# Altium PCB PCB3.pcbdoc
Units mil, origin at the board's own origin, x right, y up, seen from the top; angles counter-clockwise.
Board outline 1949.7 x 1974.5 mil, 4 copper layers (Top Layer, Inner1, Inner2, Bottom Layer); 20 components, 15 nets, 76 pads, 43 vias.
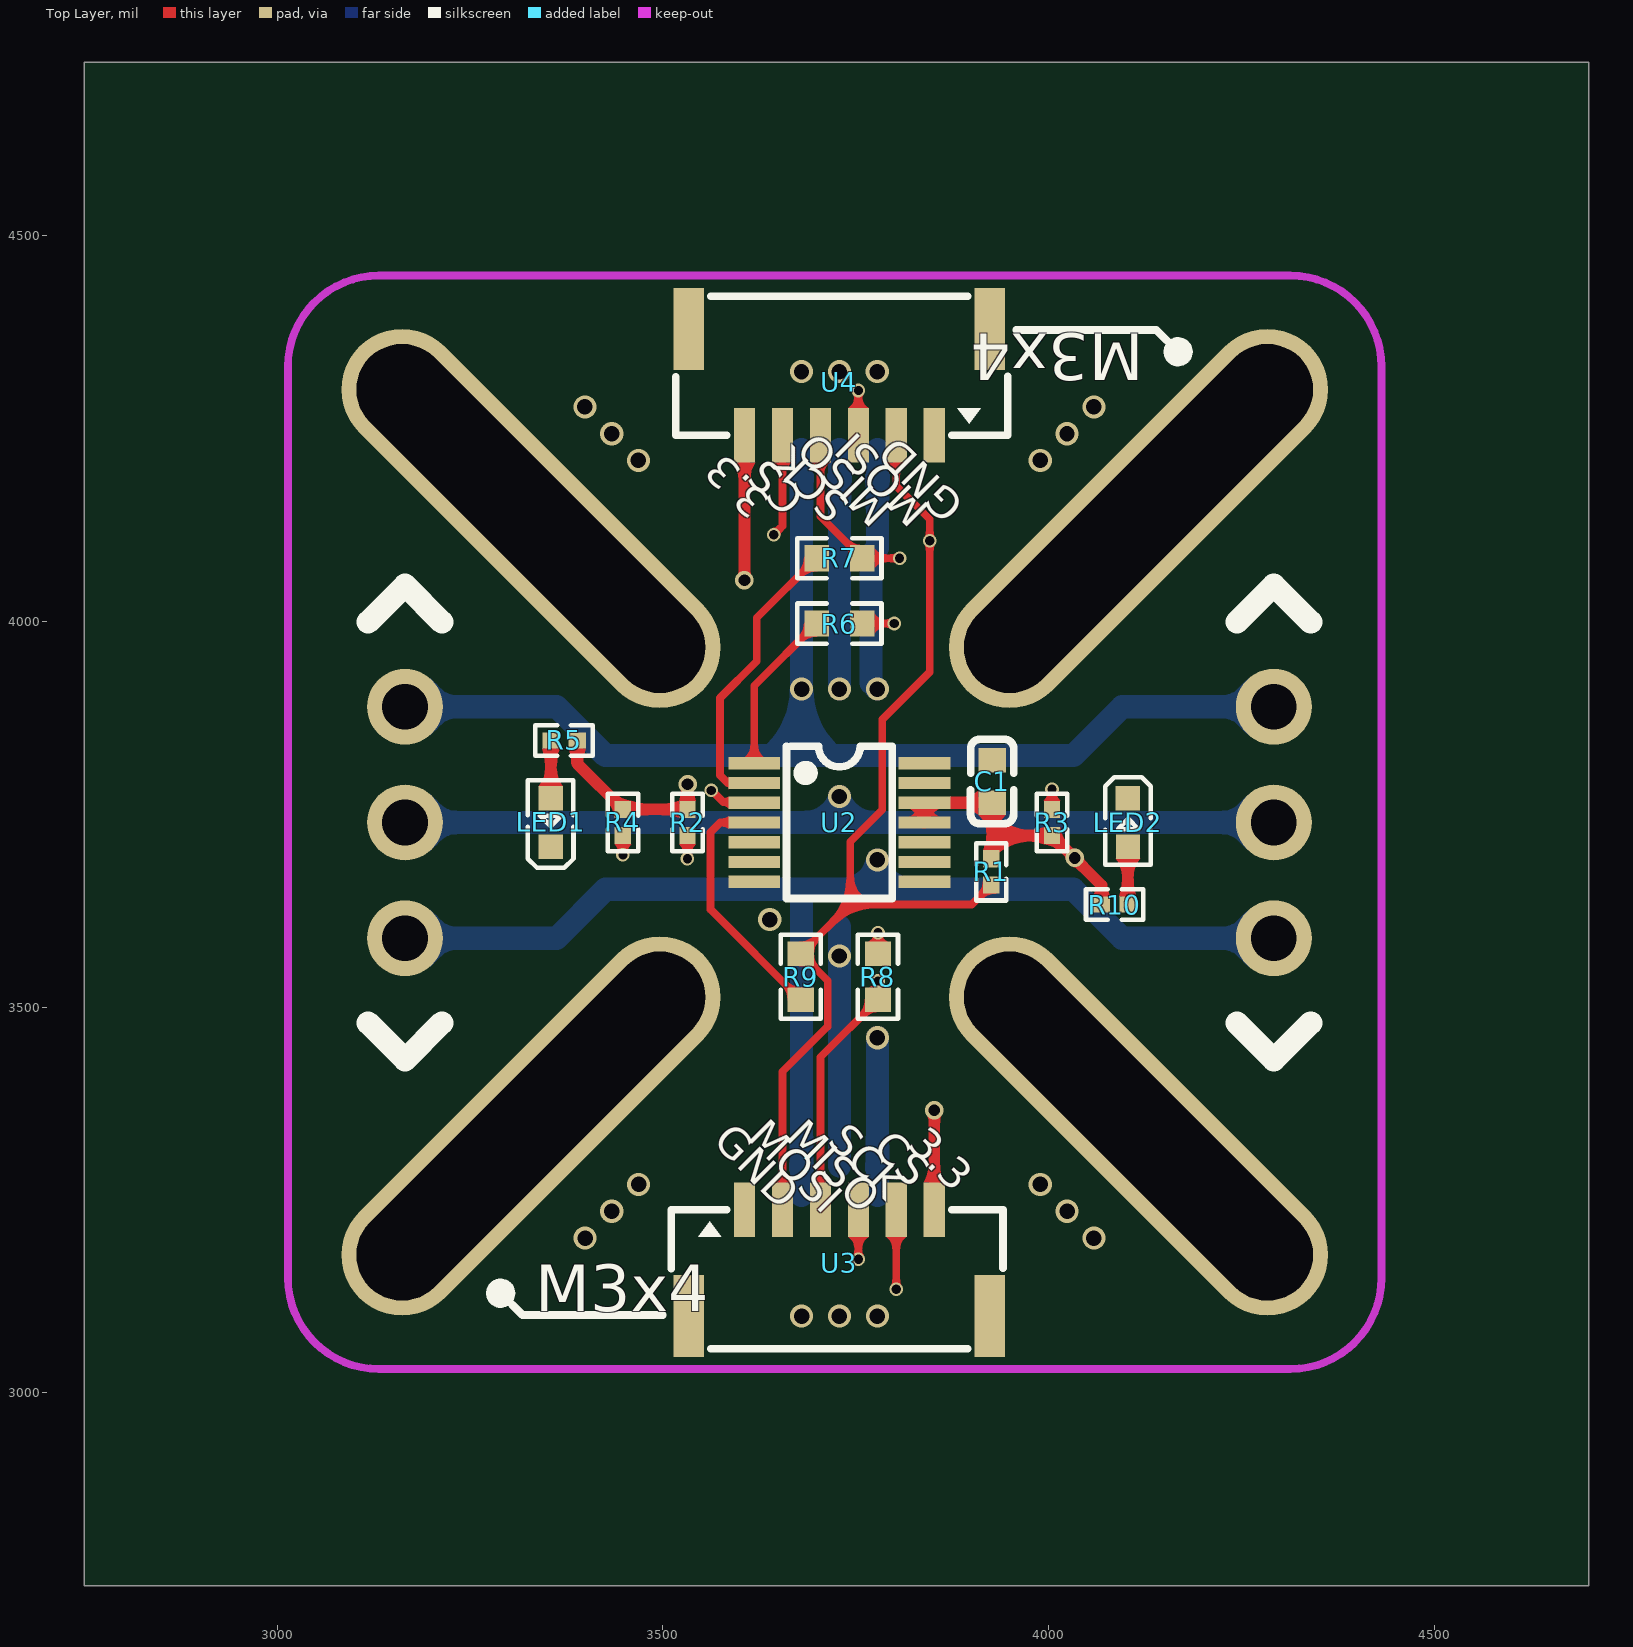
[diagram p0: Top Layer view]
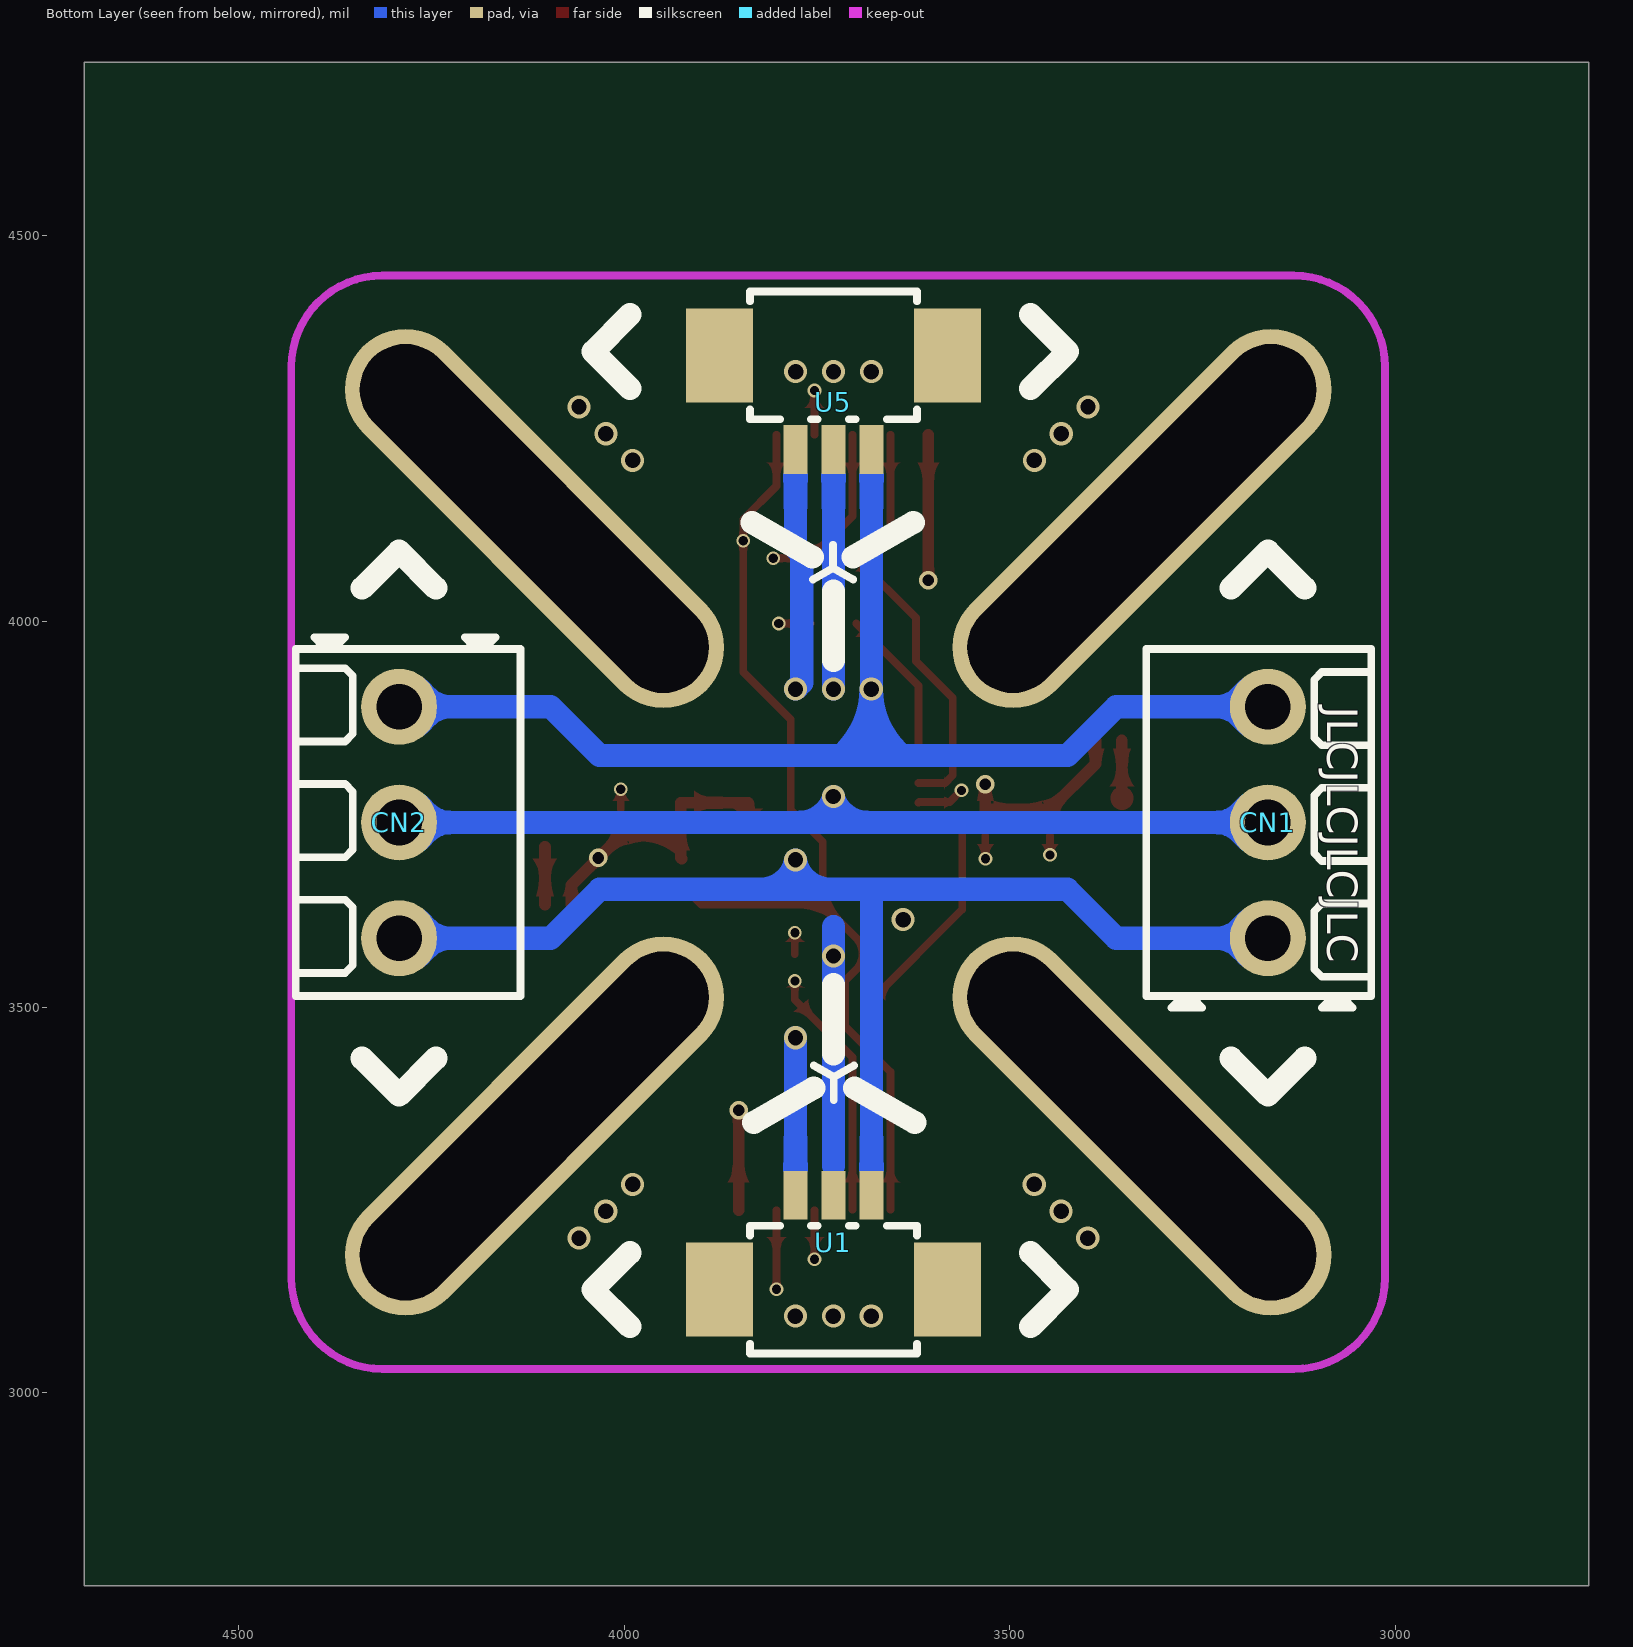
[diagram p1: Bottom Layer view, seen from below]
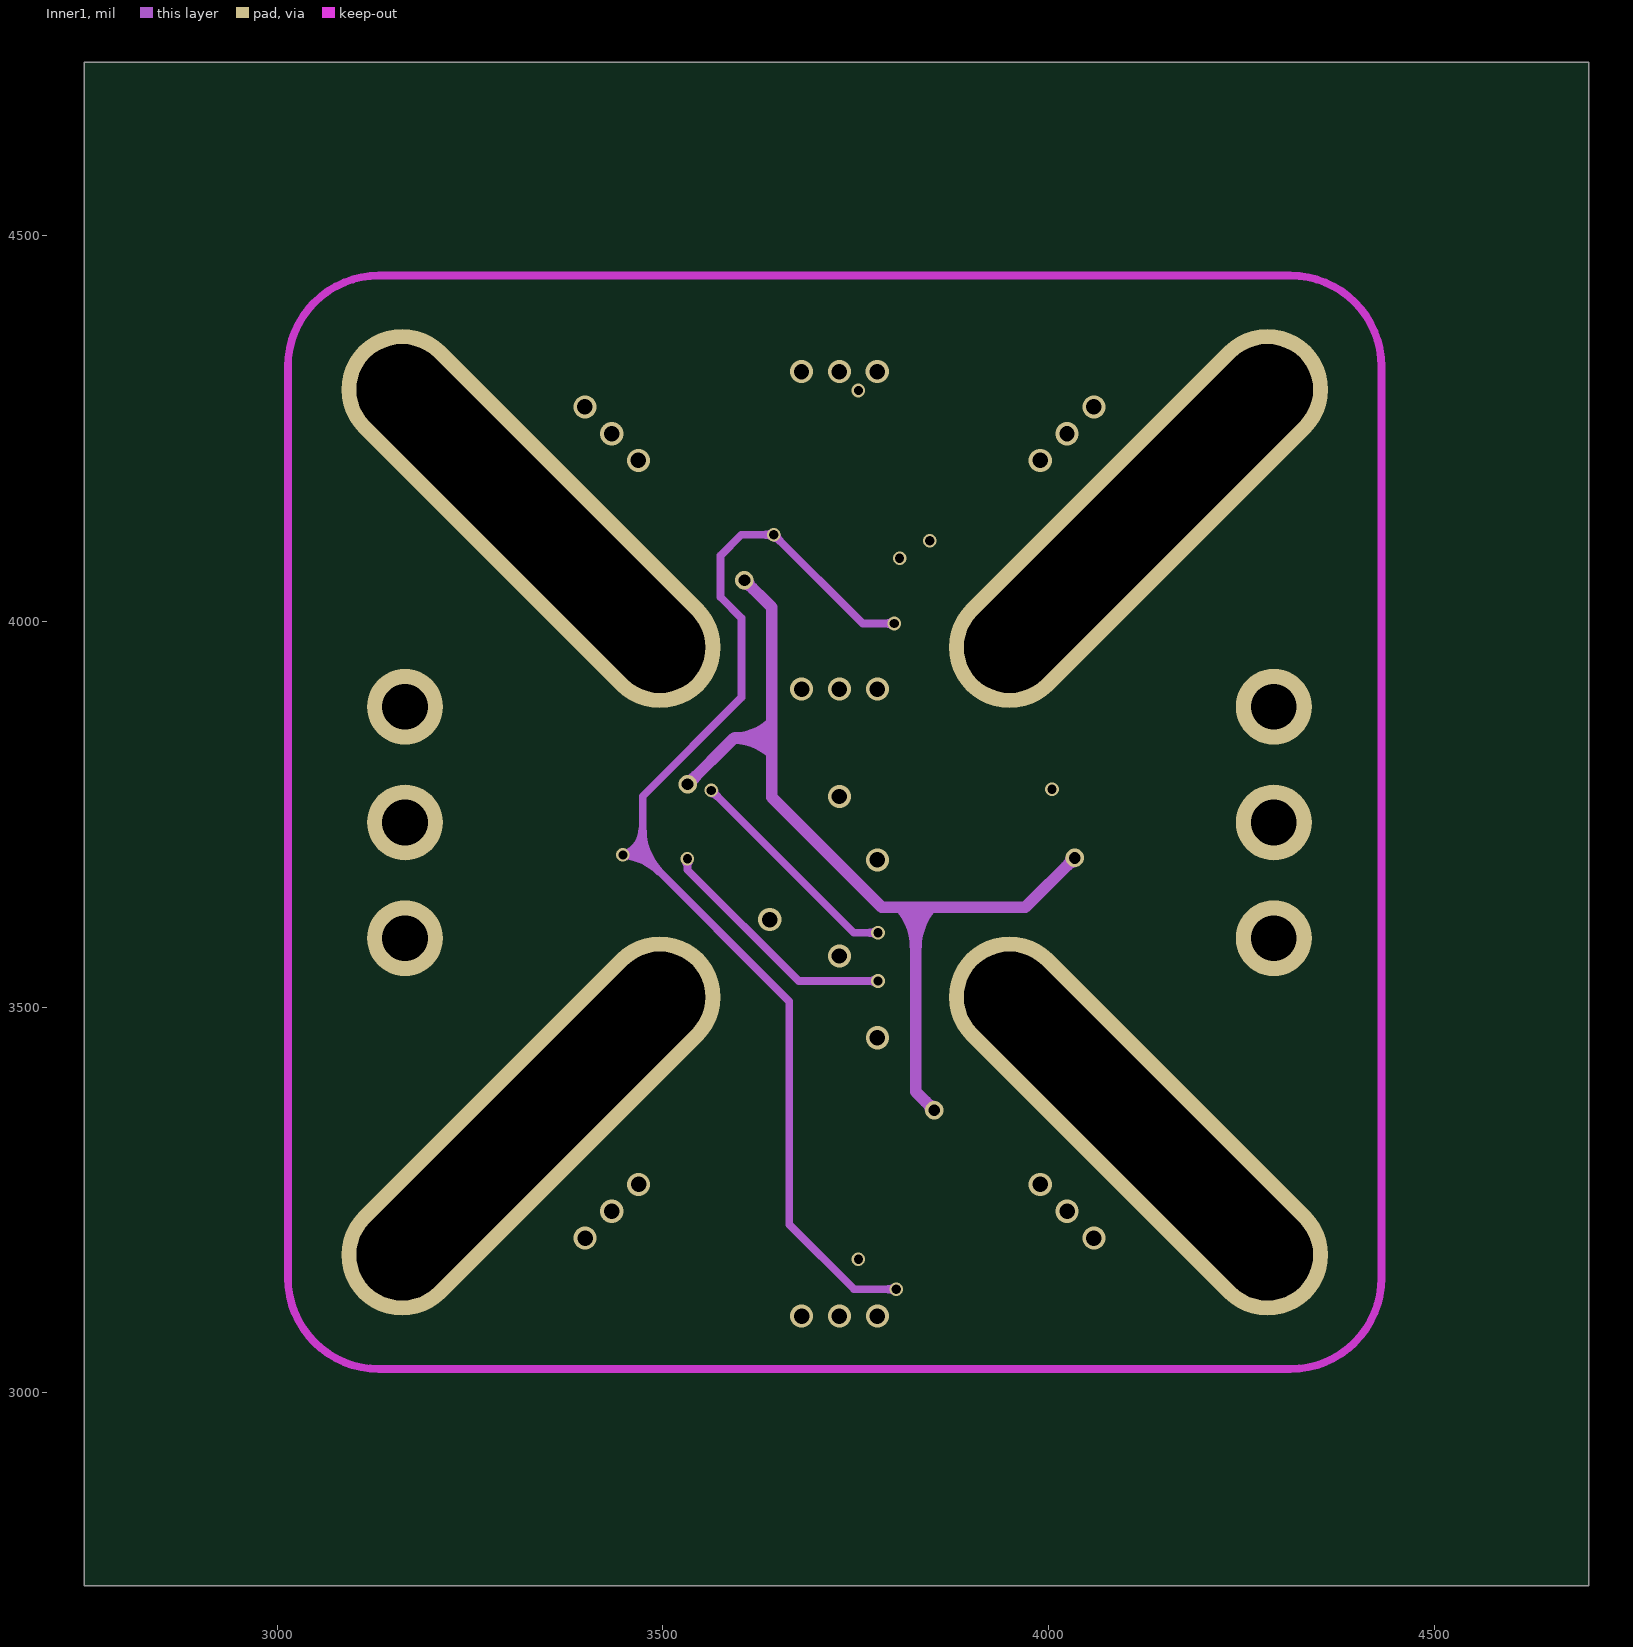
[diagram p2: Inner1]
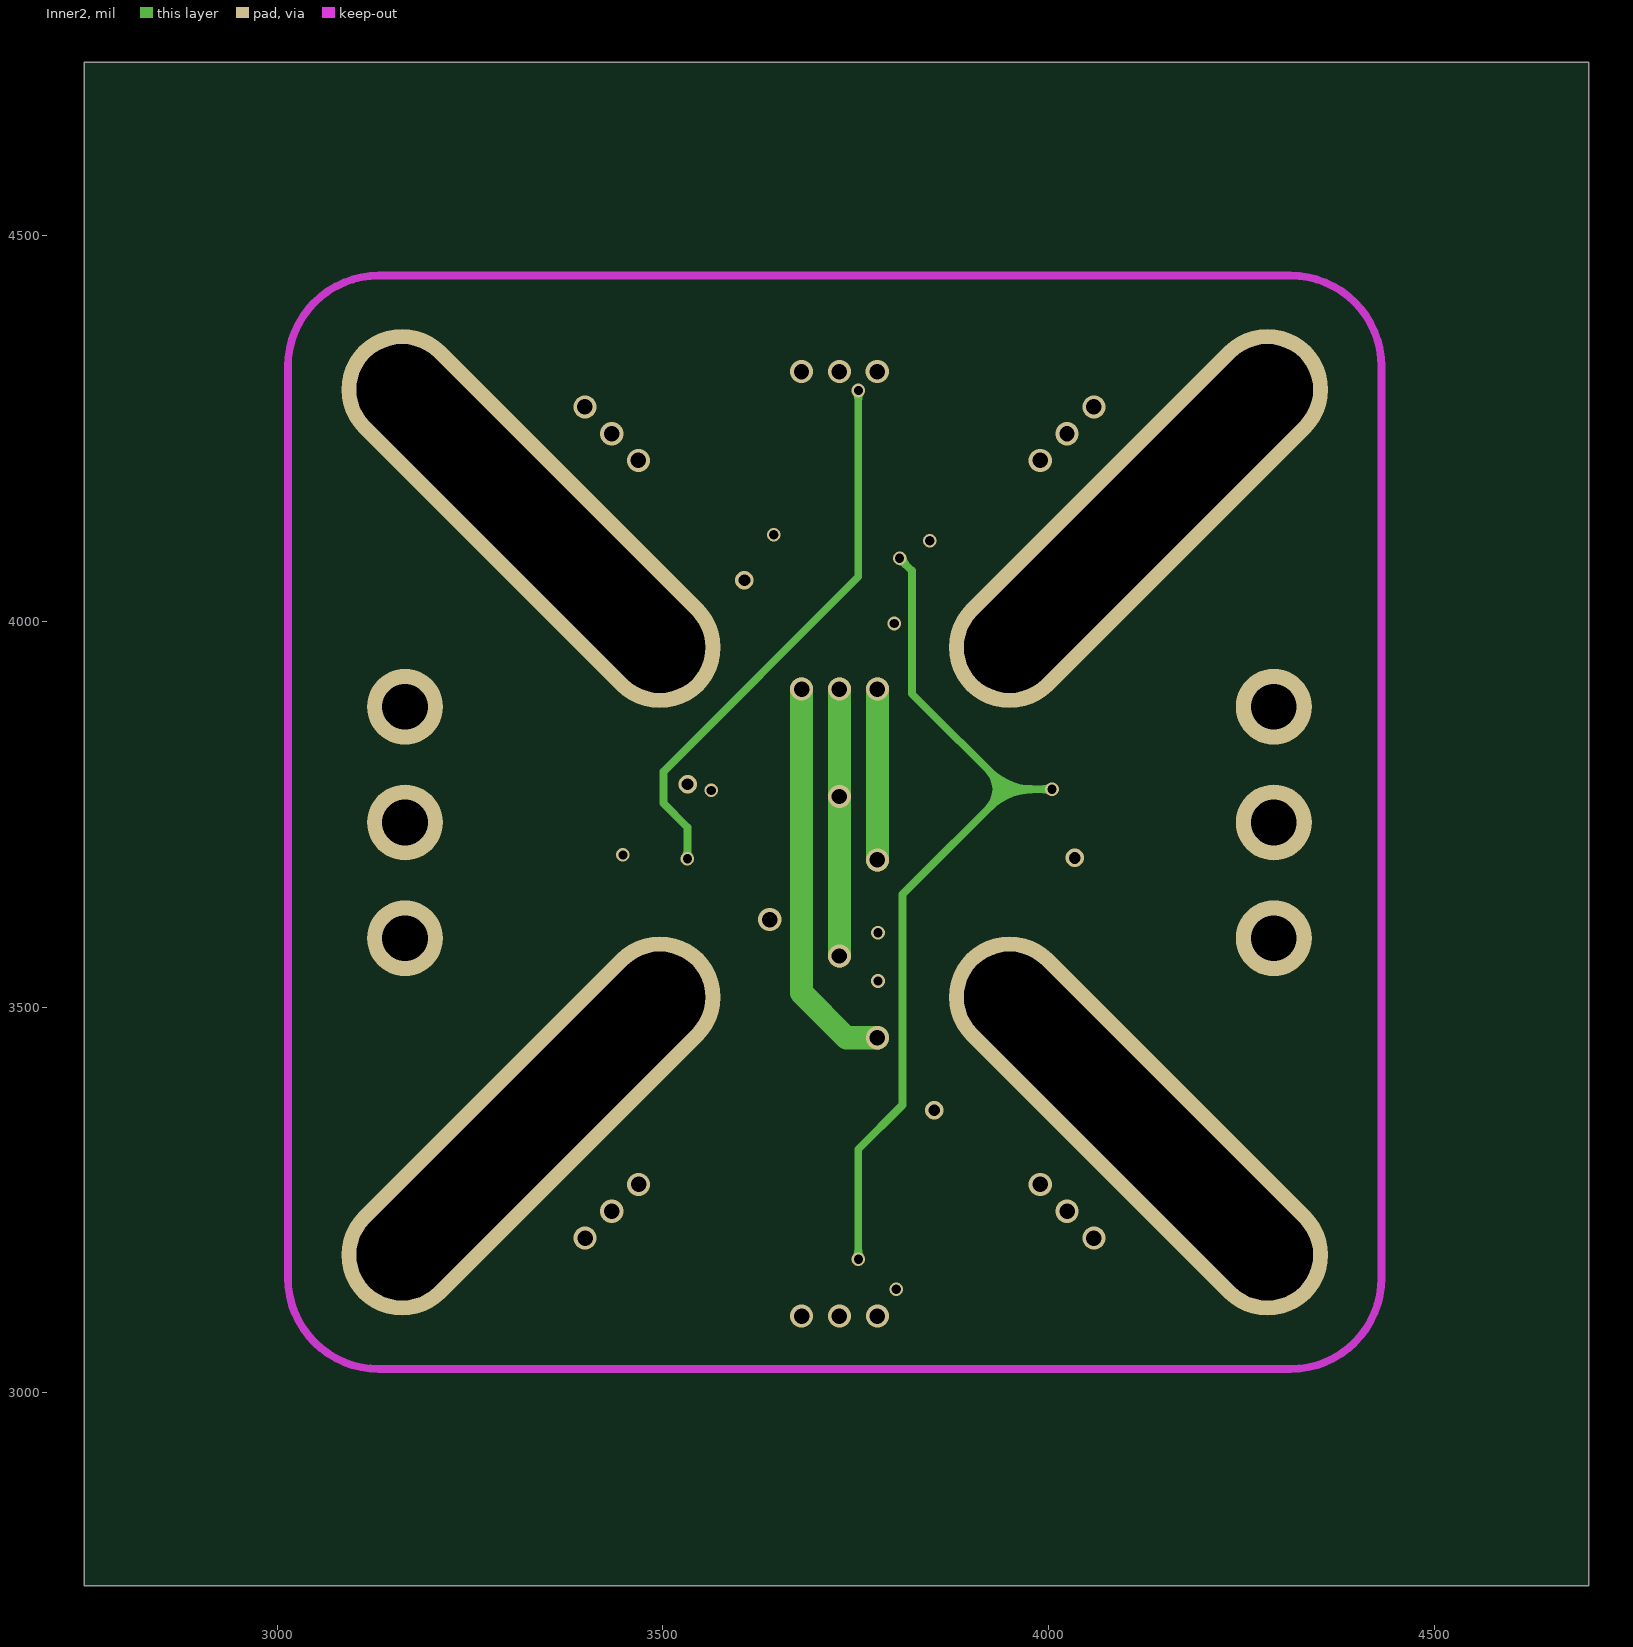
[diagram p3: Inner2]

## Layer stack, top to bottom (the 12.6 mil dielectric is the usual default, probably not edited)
Top Layer: signal copper (thickness not stored)
Dielectric: dielectric 12.6, FR-4, Dk 4.8
Inner1: signal copper (thickness not stored)
Dielectric: dielectric 12.6, FR-4, Dk 4.8
Inner2: signal copper (thickness not stored)
Dielectric: dielectric 12.6, FR-4, Dk 4.8
Bottom Layer: signal copper (thickness not stored)

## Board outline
4699.7,2750 2750,2750 2750,4724.5 4699.7,4724.5

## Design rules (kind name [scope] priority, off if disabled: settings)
BoardOutlineClearance copperThickness1oz [All] p0: genericclearance=10 ignorepadtopadclearanceinfootprint=FALSE except(0: Arc-SplitContinuation Track-SplitContinuation SMDPad-SplitContinuation THPad-SplitContinuation Via-SplitContinuation Fill-SplitContinuation Poly-SplitContinuation Region-SplitContinuation Text-SplitContinuation; 6: Track-CutoutEdge SMDPad-CutoutEdge THPad-CutoutEdge Via-CutoutEdge Region-CutoutEdge; 11.8: Track-OutlineEdge SMDPad-OutlineEdge THPad-OutlineEdge Via-OutlineEdge Fill-OutlineEdge Region-OutlineEdge Poly-OutlineEdge Text-OutlineEdge Fill-CutoutEdge)
BoardOutlineClearance copperThickness2oz [All] p0: genericclearance=10 ignorepadtopadclearanceinfootprint=FALSE except(0: Arc-SplitContinuation Track-SplitContinuation SMDPad-SplitContinuation THPad-SplitContinuation Via-SplitContinuation Fill-SplitContinuation Poly-SplitContinuation Region-SplitContinuation Text-SplitContinuation; 6: Track-CutoutEdge SMDPad-CutoutEdge THPad-CutoutEdge Via-CutoutEdge Region-CutoutEdge; 11.8: Track-OutlineEdge SMDPad-OutlineEdge THPad-OutlineEdge Via-OutlineEdge Fill-OutlineEdge Region-OutlineEdge Poly-OutlineEdge Text-OutlineEdge Fill-CutoutEdge)
Clearance copperThickness1oz [(InNet('$1N1242') OR InNet('MOSI') OR InNet('MISO') OR InNet('CLK') OR InNet('CSN') OR InNet('+3.3V_1') OR InNet('$1N1859') OR InNet('$1N1862') OR InNet('$1N3469') OR InNet('DGND') OR InNet('U') OR InNet('V') OR InNet('W') OR InNet('$1N5462') OR InNet('$1N5453'))] p1: gap=7 ignorepadtopadclearanceinfootprint=FALSE except(4: Track-Track; 6: Track-SMDPad SMDPad-SMDPad Track-THPad SMDPad-THPad THPad-THPad Track-Via SMDPad-Via THPad-Via Via-Via SMDPad-Fill THPad-Fill Via-Fill Fill-Fill Track-Region SMDPad-Region THPad-Region Via-Region Region-Region Track-Poly SMDPad-Poly THPad-Poly Via-Poly Fill-Poly Region-Poly Poly-Poly Track-Text SMDPad-Text THPad-Text Via-Text Fill-Text Region-Text Poly-Text Text-Text; 6.9: Track-Hole SMDPad-Hole THPad-Hole Via-Hole Fill-Hole Region-Hole Poly-Hole Text-Hole Sheet-Hole; 11.8: Track-Fill Fill-Region Track-Sheet SMDPad-Sheet THPad-Sheet Via-Sheet Fill-Sheet Region-Sheet Poly-Sheet Text-Sheet)
Clearance copperThickness2oz [All] p1: gap=7 ignorepadtopadclearanceinfootprint=FALSE except(6: Track-SMDPad SMDPad-SMDPad Track-THPad SMDPad-THPad THPad-THPad Track-Via SMDPad-Via THPad-Via Via-Via SMDPad-Fill THPad-Fill Via-Fill Fill-Fill Track-Region SMDPad-Region THPad-Region Via-Region Region-Region Track-Poly SMDPad-Poly THPad-Poly Via-Poly Fill-Poly Region-Poly Poly-Poly Track-Text SMDPad-Text THPad-Text Via-Text Fill-Text Region-Text Poly-Text Text-Text; 6.9: Track-Hole SMDPad-Hole THPad-Hole Via-Hole Fill-Hole Region-Hole Poly-Hole Text-Hole Sheet-Hole; 8: Track-Track; 11.8: Track-Fill Fill-Region Track-Sheet SMDPad-Sheet THPad-Sheet Via-Sheet Fill-Sheet Region-Sheet Poly-Sheet Text-Sheet)
DiffPairsRouting differentialPair [All] p1: maxuncoupledlength=10 minlimit=6 maxlimit=6 mostfreqgap=6 toplayer_minwidth=5 toplayer_prefwidth=10 toplayer_maxwidth=100 bottomlayer_minwidth=5 bottomlayer_prefwidth=10 bottomlayer_maxwidth=100 midlayer1_minwidth=5 midlayer1_prefwidth=10 midlayer1_maxwidth=100 midlayer2_minwidth=5 midlayer2_prefwidth=10 midlayer2_maxwidth=100
PasteMaskExpansion pasteMaskExpansion [All] p1: expansion=0
PlaneConnect innerPlane [All] p1: planeconnectstyle=Relief reliefexpansion=20 reliefentries=4 reliefconductorwidth=10 reliefairgap=10
PolygonConnect copperRegion [All] p1: connectstyle=Relief reliefentries=4 reliefconductorwidth=10 polygonreliefangle="90 Angle" airgapwidth=10
RoutingVias viaSize [All] p1: viastyle="Through Hole" holewidth=12 minholewidth=11.8 maxholewidth=248 width=24 minwidth=17.7 maxwidth=393.7
SolderMaskExpansion solderMaskExpansion [All] p1: useseparateexpansions=TRUE expansion=2 expansionbottom=2
Width copperThickness1oz [All] p1: maxlimit=100 minlimit=5 preferedwidth=10
Width copperThickness2oz [All] p1: maxlimit=100 minlimit=8 preferedwidth=10

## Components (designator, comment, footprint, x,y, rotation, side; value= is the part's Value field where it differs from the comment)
C1 "CGA0603X7R104K500JT" C0603 3926.69,3792.36 r270 top
CN1 "DB125-3.81-3P-RD-S" CONN-TH_3P-P3.81_L7.4-W11.4 3165.69,3739.2 r90 bottom
CN2 "DB125-3.81-3P-RD-S" CONN-TH_3P-P3.81_L7.4-W11.4 4291.69,3739.2 r270 bottom
LED1 "XL-1608UBC-04" LED0603-RD_BLUE 3354.68,3739.2 r90 top
LED2 "XL-1608UBC-04" LED0603-RD_BLUE 4102.71,3739.2 r270 top
R1 "0402WGF1002TCE" R0402 3925.54,3675.24 r270 top
R2 "0402WGF1002TCE" R0402 3531.84,3739.2 r270 top
R3 "0402WGF1002TCE" R0402 4004.28,3739.2 r270 top
R4 "0402WGF1002TCE" R0402 3448.12,3739.2 r270 top
R5 "FRC0402J102 TS" R0402 3371.87,3845.5 r0 top
R6 "0603WAF220JT5E" R0603 3728.69,3997.09 r0 top
R7 "0603WAF220JT5E" R0603 3728.69,4081.74 r0 top
R8 "0603WAF220JT5E" R0603 3778.69,3539.2 r270 top
R9 "0603WAF220JT5E" R0603 3678.69,3539.2 r90 top
R10 "FRC0402J102 TS" R0402 4085.5,3632.9 r180 top
U1 "532610371" CONN-TH_532610371 3728.69,3194.8 r180 bottom
U2 "AS5047P-ATSM_C962063" TSSOP-14_L5.0-W4.4-P0.65-LS6.4-BL 3728.69,3739.2 r270 top
U3 "HC-GH-6PWT" CONN-SMD_6P-P1.25_HCTL_HC-GH-6PWT 3728.69,3168.3 r0 top
U4 "HC-GH-6PWT" CONN-SMD_6P-P1.25_HCTL_HC-GH-6PWT 3728.69,4310.1 r180 top
U5 "532610371" CONN-TH_532610371 3728.69,4283.6 r0 bottom

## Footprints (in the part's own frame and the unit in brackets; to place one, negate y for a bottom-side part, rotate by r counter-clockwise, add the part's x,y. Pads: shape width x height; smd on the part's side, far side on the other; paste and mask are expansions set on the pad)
C0603 [mm]
  rect 0.8x0.9 smd: 1(-0.7,0) 2(0.7,0)
  silkscreen extent -1.39,-0.71 1.39,0.71
CONN-SMD_6P-P1.25_HCTL_HC-GH-6PWT [mm]
  rect 0.7x1.8 smd: 1(-3.125,1.75) 2(-1.875,1.75) 3(-0.625,1.75) 4(0.625,1.75) 5(1.875,1.75) 6(3.125,1.75)
  rect 1x2.7 smd: 7(4.955,-1.75) 8(-4.955,-1.75)
  silkscreen extent -5.54,-2.82 5.38,1.75
CONN-TH_3P-P3.81_L7.4-W11.4 [mm]
  round 2.5 hole 1.5: 1(-3.81,0) 2(0,0) 3(3.81,0)
  silkscreen extent -6.1,-3.4 5.71,4
CONN-TH_532610371 [mm]
  rect 0.8x1.6 smd: 1(-1.25,1.55) 2(0,1.55) 3(1.25,1.55)
  rect 2.2x3.1 smd: 4(3.75,-1.55) 5(-3.75,-1.55)
  silkscreen extent -2.75,-3.65 2.75,0.55
LED0603-RD_BLUE [mil]
  rect 31.5x31.5 smd: 1(-31.5,-0.1) 2(31.5,0.1)
  silkscreen extent -59,-29 55,30
R0402 [mm]
  rect 0.566x0.54 smd: 1(-0.433,0) 2(0.433,0)
  silkscreen extent -0.94,-0.5 0.94,0.5
R0603 [mil]
  rect 31.75x34.02 smd: 1(-29.66,0) 2(29.66,0)
  silkscreen extent -55,-26 55,26
TSSOP-14_L5.0-W4.4-P0.65-LS6.4-BL [mm]
  rect 0.4x1.7 smd: 1(-1.95,-2.8) 2(-1.3,-2.8) 3(-0.65,-2.8) 4(0,-2.8) 5(0.65,-2.8) 6(1.3,-2.8) 7(1.95,-2.8) 8(1.95,2.8) 9(1.3,2.8) 10(0.65,2.8) 11(0,2.8) 12(-0.65,2.8) 13(-1.3,2.8) 14(-1.95,2.8)
  silkscreen extent -2.51,-1.74 2.5,1.74

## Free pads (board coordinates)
  oval 629.92x157.48 hole 118.11 slot 590.55 at 45 deg rot 45: 1(3328.91,3345.79) 1(4116.31,4133.19)
  oval 629.92x157.48 hole 118.11 slot 590.55 at 135 deg rot 135: 1(3328.91,4133.19) 1(4116.31,3345.79)

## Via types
v1: diameter 30, hole 20, Top Layer to Bottom Layer, 26 vias
v2: diameter 17.7, hole 12, Top Layer to Bottom Layer, 13 vias
v3: diameter 24, hole 15, Top Layer to Bottom Layer, 4 vias

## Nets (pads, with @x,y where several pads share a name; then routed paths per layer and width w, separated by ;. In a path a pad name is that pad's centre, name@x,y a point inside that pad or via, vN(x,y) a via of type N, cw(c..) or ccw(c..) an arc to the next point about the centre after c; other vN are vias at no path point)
$1N1242: R2.2 R8.2 U3.3 U4.3 | length 1459.2
  Top Layer w10: v2(3531.69,3692.2) 3531.84,3692.35 R2.2 ; U3.3 3704.08,3434.93 R8.2 v2(3778.69,3533.79) ; U4.3@3753.3,4241.86 v2(3753.3,4299.2)
  Inner1 w10: v2(3531.69,3692.2) 3531.69,3678.06 3675.96,3533.79 v2@3777.67,3533.79
  Inner2 w10: v2(3531.69,3692.2) 3531.69,3733.2 3500.69,3764.2 3500.69,3805.2 3753.3,4057.81 v2(3753.3,4299.2)
$1N1859: LED1.2 R5.1 | length 74.9
  Top Layer w15: LED1.2@3354.83,3770.96 R5.1
  Top Layer w30: LED1.2 LED1.2@3354.83,3770.96
$1N1862: LED2.2 R10.1 | length 74.9
  Top Layer w15: R10.1 4102.54,3707.44 LED2.2
$1N3469: R4.2 R6.2 U3.5 U4.5 | length 1795.9
  Top Layer w10: v2(3448.12,3697.2) R4.2 ; v2(3643.69,4112.2) 3654.87,4123.38 U4.5@3654.87,4241.86 ; R6.2 v2(3799.69,3997.09) ; v2(3802.51,3134.2) U3.5@3802.51,3236.51
  Inner1 w10: v2(3448.12,3697.2) 3473.69,3697.2 ; v2(3799.69,3997.09) 3758.81,3997.09 v2(3643.69,4112.2) 3601.69,4112.2 3574.69,4085.2 3574.69,4031.2 3601.69,4004.2 3601.69,3901.2 3473.69,3773.2 3473.69,3697.2 ; v2(3802.51,3134.2) 3747.69,3134.2 3663.69,3218.2 3663.69,3507.2 3473.69,3697.2
$1N5453: R3.1 R7.2 U3.4 U4.4 | length 1424.4
  Top Layer w10: U4.4@3704.08,4241.86 3704.08,4136.01 R7.2 v2(3806.69,4081.74) ; v2(3753.3,3173.2) U3.4@3753.3,3236.51 ; R3.1 v2(4004.28,3782.2)
  Inner2 w10: v2(3753.3,3173.2) 3753.3,3315.81 3810.52,3373.02 3810.52,3646.02 3946.69,3782.2 ; v2(3806.69,4081.74) 3822.69,4065.74 3822.69,3906.2 3946.69,3782.2 ; v2(4004.28,3782.2) 3946.69,3782.2
$1N5462: R1.2 R9.2 U3.2 U4.2 | length 1323.9
  Top Layer w10: U3.2 3654.87,3416.11 3713.69,3474.93 3713.69,3533.86 R9.2 3742.69,3632.86 ; U4.2@3802.51,4241.86 3802.51,4175.38 3845.69,4132.2 v2(3845.69,4104.2) 3845.69,3934.2 3784.19,3872.7 3784.19,3755.7 3742.69,3714.2 3742.69,3632.86 ; R1.2 3900.21,3632.86 3742.69,3632.86
+3.3V_1: C1.2 R1.1 R2.1 R3.2 R4.1 R5.2 R10.2 U2.11 U2.12 U3.6 U4.6 | length 2108.9
  Top Layer w15: R5.2 3388.91,3815.45 R4.1 R2.1 v3(3531.84,3788.5) ; v3(3605.66,4053.23) U4.6@3605.66,4241.86 ; U2.11 U2.12 C1.2 3926.69,3722.16 ; U3.6@3851.72,3236.51 v3(3851.72,3366.14) ; R1.1 3926.69,3693.43 3926.69,3722.16 ; R10.2 4068.46,3657.98 R3.2 3926.69,3722.16
  Inner1 w15: v3(3531.84,3788.5) 3591.88,3848.53 3640.81,3848.53 ; v3(3605.66,4053.23) 3640.81,4018.08 3640.81,3848.53 ; v3(3851.72,3366.14) 3827.69,3390.17 3827.69,3629.2 ; v3(4033.69,3693.2) 3969.69,3629.2 3827.69,3629.2 ; 3640.81,3848.53 3640.81,3772.08 3783.69,3629.2 3827.69,3629.2
CLK: R7.1 U2.2 | length 381.7
  Top Layer w10: U2.2 3584,3790.38 3574,3800.38 3574,3900.51 3621.69,3948.2 3621.69,4004.4 R7.1
CSN: R6.1 U2.1 | length 214.5
  Top Layer w10: U2.1 3618.45,3916.51 R6.1
DGND: C1.1 LED1.1 LED2.1 U2.5 U2.13 U3.1 U4.1
  other v1: 3679.73,3099.43 3728.77,3099.43 3777.98,3099.43 3399.03,3200.58 4058.53,3200.59 3433.7,3235.26 4023.85,3235.26 3468.5,3270.06 3989.05,3270.06 3638.38,3613.28 3468.23,4208.46 3989.03,4208.45 3433.55,4243.13 4023.7,4243.13 3398.75,4277.93 4058.5,4277.93 3679.59,4323.51 3728.63,4323.51 3777.84,4323.51
MISO: R8.1 U2.3 | length 382.2
  Top Layer w10: v2(3562.69,3780.79) 3562.94,3780.79 3578.03,3765.71 3617.54,3765.71 U2.3 ; R8.1 v2(3778.69,3596.2)
  Inner1 w10: v2(3562.69,3780.79) 3747.28,3596.2 v2(3778.69,3596.2)
MOSI: R9.1 U2.4 | length 327.6
  Top Layer w10: U2.4 3574.2,3739.2 3561.69,3726.69 3561.69,3626.54 R9.1
U: CN1.3 CN2.1 U1.1 U5.1 | length 2295.6
  Inner2 w30: v1(3679.65,3912.16) 3679.65,3518.21 3737.69,3460.17 v1(3777.9,3460.17)
  Bottom Layer w30: CN1.3 3362.16,3889.2 3425.54,3825.81 4031.84,3825.81 4095.23,3889.2 CN2.1 ; U5.1 3679.48,3912.33 v1(3679.65,3912.16) 3679.65,3826.19 ; U1.1 v1(3777.9,3460.17)
V: CN1.2 CN2.2 U1.2 U5.2 | length 2126.4
  Inner2 w30: v1(3728.69,3566.17) v1(3728.7,3772.9) v1(3728.69,3912.17)
  Bottom Layer w30: CN1.2 3728.7,3739.2 ; 3728.69,3293.82 v1(3728.69,3566.17) 3728.69,3604.17 ; v1(3728.7,3772.9) 3728.7,3739.2 ; v1(3728.69,3912.17) U5.2 ; CN2.2 3728.7,3739.2
W: CN1.1 CN2.3 U1.3 U5.3 | length 2151.2
  Inner2 w30: v1(3777.9,3690.79) v1(3777.9,3912.17)
  Bottom Layer w30: CN1.1 3362.16,3589.2 3425.54,3652.59 3777.9,3652.59 ; U1.3 3679.48,3651.84 ; v1(3777.9,3690.79) 3777.9,3652.59 ; v1(3777.9,3912.17) 3769.84,3920.23 3769.84,4087.1 3777.9,4095.16 U5.3 ; CN2.3 4095.23,3589.2 4031.84,3652.59 3777.9,3652.59
pads on no net: U1.4 U1.5 U2.6 U2.7 U2.8 U2.9 U2.10 U2.14 U3.7 U3.8 U4.7 U4.8 U5.4 U5.5

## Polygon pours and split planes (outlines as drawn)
DGND on Top Layer (solid, remove dead copper, pour order 0): 3000,4474.5 4449.7,4474.5 4449.7,3000 3000,3000
DGND on Inner1 (solid, remove dead copper): 3000,4474.5 4449.7,4474.5 4449.7,3000 3000,3000
DGND on Inner2 (solid, remove dead copper): 3000,4474.5 4449.7,4474.5 4449.7,3000 3000,3000
DGND on Bottom Layer (solid, remove dead copper, pour order 2): 3000,4474.5 4449.7,4474.5 4449.7,3000 3000,3000

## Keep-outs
Board Outline Layer:
  lines w10: 3013.95,3148.94 3013.95,4330.04 cw(c3132.06,4330.04) 3132.06,4448.15 4313.16,4448.15 cw(c4313.16,4330.04) 4431.27,4330.04 4431.27,3148.94 cw(c4313.16,3148.94) 4313.16,3030.83 3132.06,3030.83 cw(c3132.06,3148.94) 3013.95,3148.94

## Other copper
Top Layer:
  region net +3.3V_1: 3886.48,3757.29 3886.48,3772.29 ccw(c3886.48,3807.07) 3908.98,3780.55 3908.98,3749.05 ccw(c3886.48,3722.44)
  region net +3.3V_1: 3934.19,3726.55 3919.19,3726.55 ccw(c3889.31,3726.55) 3908.98,3749.05 3944.41,3749.05 ccw(c3964.08,3726.55)
  region net $1N3469: 3789.23,4002.09 3789.23,3992.09 ccw(c3789.23,3973.34) 3774.23,3984.59 3774.23,4009.59 ccw(c3789.23,4020.84)
  region net CSN: 3683.79,3974.78 3677.85,3982.98 ccw(c3656.64,3998.89) 3683.16,3998.89 3699.7,3980.08 ccw(c3699.7,3953.56)
  region net $1N5453: 3789.23,4086.74 3789.23,4076.74 ccw(c3789.23,4057.99) 3774.23,4069.24 3774.23,4094.24 ccw(c3789.23,4105.49)
  region net $1N5453: 3737.17,4095.84 3743.11,4104.05 ccw(c3759.02,4125.26) 3759.02,4098.74 3742.48,4079.93 ccw(c3715.96,4079.93)
  region net CLK: 3683.79,4059.43 3677.85,4067.63 ccw(c3656.64,4083.54) 3683.16,4083.54 3699.7,4064.73 ccw(c3699.7,4038.21)
  region net $1N1242: 3764.58,3488.36 3756.38,3494.3 ccw(c3735.17,3510.21) 3761.68,3510.21 3780.49,3493.66 ccw(c3780.49,3467.15)
  region net $1N1242: 3773.69,3533.79 3783.69,3533.79 ccw(c3792.12,3533.79) 3791.19,3525.42 3766.19,3525.42 ccw(c3765.27,3533.79)
  region net MISO: 3773.69,3596.2 3783.69,3596.2 ccw(c3796.2,3596.2) 3791.19,3584.74 3766.19,3584.74 ccw(c3761.18,3596.2)
  region net $1N5462: 3701,3553.62 3692.8,3547.68 ccw(c3676.89,3526.47) 3676.89,3552.98 3695.7,3569.53 ccw(c3722.22,3569.53)
  region net $1N5462: 3692.8,3590.04 3701,3584.1 ccw(c3722.22,3568.19) 3695.7,3568.19 3676.89,3584.74 ccw(c3676.89,3611.25)
  region net MOSI: 3656.38,3524.78 3664.58,3530.72 ccw(c3680.49,3551.93) 3680.49,3525.42 3661.68,3508.87 ccw(c3635.17,3508.87)
  region net +3.3V_1: 3971.15,3714.66 3971.15,3729.66 ccw(c3971.15,3801.11) 3993.65,3733.3 3993.65,3711.03 ccw(c3971.15,3643.21)
  region net +3.3V_1: 4025.24,3711.81 4015.14,3700.69 ccw(c3989.67,3675.22) 3993.65,3711.03 4014.91,3733.3 ccw(c4050.72,3737.28)
  region net $1N5453: 3999.28,3782.2 4009.28,3782.2 ccw(c4031.62,3782.2) 4014.91,3767.38 3993.65,3767.38 ccw(c3976.95,3782.2)
  region net $1N5462: 3916.18,3641.76 3909.61,3649.33 ccw(c3888.4,3665.24) 3914.91,3665.24 3932.09,3647.06 ccw(c3932.09,3620.55)
  region net +3.3V_1: 3919.19,3722.16 3934.19,3722.16 ccw(c4023.93,3722.16) 3936.17,3703.41 3914.91,3703.41 ccw(c3875.99,3722.16)
  region net $1N1242: 3536.84,3696.03 3526.84,3696.03 ccw(c3504.04,3696.03) 3521.21,3711.03 3542.47,3711.03 ccw(c3559.64,3696.03)
  region net +3.3V_1: 3524.34,3788.5 3539.34,3788.5 ccw(c3612.19,3788.5) 3542.47,3767.38 3521.21,3767.38 ccw(c3451.49,3788.5)
  region net +3.3V_1: 3498.71,3748.74 3498.71,3763.74 ccw(c3498.71,3835.19) 3521.21,3767.38 3521.21,3745.11 ccw(c3498.71,3677.29)
  region net CSN: 3613.45,3838.84 3623.45,3838.84 ccw(c3642.2,3838.84) 3630.95,3823.84 3605.95,3823.84 ccw(c3594.7,3838.84)
  region net CLK: 3584,3785.38 3584,3795.38 ccw(c3580.3,3798.25) 3584.99,3798.25 3584.99,3782.51 ccw(c3580.3,3782.51)
  region net MISO: 3578.03,3760.71 3578.03,3770.71 ccw(c3578.03,3784.05) 3584.99,3772.66 3584.99,3756.92 ccw(c3578.03,3752.42)
  region net MOSI: 3574.2,3734.2 3574.2,3744.2 ccw(c3574.2,3765.88) 3584.99,3747.07 3584.99,3731.33 ccw(c3574.2,3712.52)
  region net +3.3V_1: 3831.43,3764.79 3846.43,3764.79 ccw(c3866.01,3764.79) 3857.68,3747.07 3820.18,3747.07 ccw(c3811.86,3764.79)
  region net +3.3V_1: 3846.43,3739.2 3831.43,3739.2 ccw(c3811.86,3739.2) 3820.18,3756.92 3857.68,3756.92 ccw(c3866.01,3739.2)
  region net +3.3V_1: 3894.9,3772.29 3894.9,3757.29 ccw(c3894.9,3080.3) 3872.4,3756.92 3872.4,3772.66 ccw(c3894.9,4449.28)
  region net $1N1859: 3347.33,3808.95 3362.33,3808.95 ccw(c3398,3808.95) 3370.33,3786.45 3338.83,3786.45 ccw(c3313.33,3808.95)
  region net $1N1862: 4110.04,3669.45 4095.04,3669.45 ccw(c4059.35,3669.45) 4087.06,3691.95 4118.56,3691.95 ccw(c4144.03,3669.45)
  region net +3.3V_1: 3396.41,3815.45 3381.41,3815.45 ccw(c3327.7,3815.45) 3377.78,3834.87 3400.05,3834.87 ccw(c3450.13,3815.45)
  region net $1N1859: 3362.33,3812.37 3347.33,3812.37 ccw(c3275.88,3812.37) 3343.7,3834.87 3365.97,3834.87 ccw(c3433.79,3812.37)
  region net +3.3V_1: 4060.96,3657.98 4075.96,3657.98 ccw(c4106.5,3657.98) 4079.6,3643.53 4057.33,3643.53 ccw(c4030.43,3657.98)
  region net $1N1862: 4095.04,3666.03 4110.04,3666.03 ccw(c4181.5,3666.03) 4113.68,3643.53 4091.41,3643.53 ccw(c4023.59,3666.03)
  region net $1N3469: 3453.12,3697.2 3443.12,3697.2 ccw(c3423.33,3697.2) 3437.49,3711.03 3458.75,3711.03 ccw(c3472.91,3697.2)
  region net +3.3V_1: 3427.16,3766.59 3437.26,3777.71 ccw(c3462.73,3803.18) 3458.75,3767.38 3437.49,3745.11 ccw(c3401.68,3741.12)
  region net +3.3V_1: 3481.25,3763.74 3481.25,3748.74 ccw(c3481.25,3677.29) 3458.75,3745.11 3458.75,3767.38 ccw(c3481.25,3835.19)
  region net $1N5462: 3649.87,3287.63 3659.87,3287.63 ccw(c3678.62,3287.63) 3667.37,3272.63 3642.37,3272.63 ccw(c3631.12,3287.63)
  region net $1N1242: 3699.08,3287.63 3709.08,3287.63 ccw(c3727.83,3287.63) 3716.58,3272.63 3691.58,3272.63 ccw(c3680.33,3287.63)
  region net $1N5453: 3758.3,3186.76 3748.3,3186.76 ccw(c3729.55,3186.76) 3740.8,3201.76 3765.8,3201.76 ccw(c3777.05,3186.76)
  region net $1N3469: 3807.51,3186.76 3797.51,3186.76 ccw(c3778.76,3186.76) 3790.01,3201.76 3815.01,3201.76 ccw(c3826.26,3186.76)
  region net +3.3V_1: 3844.22,3295.13 3859.22,3295.13 ccw(c3902.68,3295.13) 3865.5,3272.63 3837.94,3272.63 ccw(c3800.78,3295.13)
  region net $1N5462: 3807.51,4190.77 3797.51,4190.77 ccw(c3778.76,4190.77) 3790.01,4205.77 3815.01,4205.77 ccw(c3826.26,4190.77)
  region net $1N1242: 3748.3,4291.64 3758.3,4291.64 ccw(c3777.05,4291.64) 3765.8,4276.64 3740.8,4276.64 ccw(c3729.55,4291.64)
  region net $1N5453: 3709.08,4190.77 3699.08,4190.77 ccw(c3680.33,4190.77) 3691.58,4205.77 3716.58,4205.77 ccw(c3727.83,4190.77)
  region net $1N3469: 3659.87,4190.77 3649.87,4190.77 ccw(c3631.12,4190.77) 3642.37,4205.77 3667.37,4205.77 ccw(c3678.62,4190.77)
  region net +3.3V_1: 3613.16,4183.27 3598.16,4183.27 ccw(c3554.7,4183.27) 3591.88,4205.77 3619.44,4205.77 ccw(c3656.6,4183.27)
  region net +3.3V_1: 3539.34,3772.16 3524.34,3772.16 3524.42,3774.53 3524.42,3776.68 3524.29,3777.68 3524.01,3778.66 3523.54,3779.62 3522.84,3780.56 3540.84,3780.56 3540.14,3779.62 3539.67,3778.66 3539.39,3777.68 3539.26,3776.68 3539.26,3774.53
  region net +3.3V_1: 4016.78,3699.05 4027.05,3710 4028.68,3708.27 4030.22,3706.76 4031.04,3706.14 4031.95,3705.66 4032.96,3705.34 4034.13,3705.19 4021.74,3692.13 4021.54,3693.29 4021.17,3694.29 4020.67,3695.17 4020.04,3695.96 4018.52,3697.44
  region net +3.3V_1: 4050.49,3686.56 4039.55,3676.29 4037.93,3678.03 4036.45,3679.55 4035.66,3680.18 4034.79,3680.68 4033.79,3681.05 4032.62,3681.25 4045.68,3693.63 4045.83,3692.47 4046.15,3691.45 4046.64,3690.55 4047.25,3689.73 4048.76,3688.19
  region net +3.3V_1: 3598.16,4069.57 3613.16,4069.57 3613.08,4067.19 3613.08,4065.05 3613.21,4064.05 3613.49,4063.07 3613.96,4062.11 3614.66,4061.17 3596.66,4061.17 3597.36,4062.11 3597.83,4063.07 3598.11,4064.05 3598.24,4065.05 3598.24,4067.19
  region net +3.3V_1: 3859.22,3349.8 3844.22,3349.8 3844.3,3352.17 3844.3,3354.31 3844.17,3355.32 3843.89,3356.3 3843.42,3357.25 3842.72,3358.2 3860.72,3358.2 3860.02,3357.25 3859.55,3356.3 3859.27,3355.32 3859.14,3354.31 3859.14,3352.17
  region net $1N5462: 3850.69,4092.15 3840.69,4092.15 3840.64,4093.81 3840.41,4095.45 3839.92,4097 3839.05,4098.35 3852.33,4098.35 3851.47,4097 3850.97,4095.45 3850.75,4093.81
  region net $1N5462: 3840.69,4116.25 3850.69,4116.25 3850.75,4114.59 3850.97,4112.95 3851.47,4111.4 3852.33,4110.05 3839.05,4110.05 3839.92,4111.4 3840.41,4112.95 3840.64,4114.59
  region net $1N3469: 3648.68,4124.26 3655.75,4117.18 3654.62,4115.98 3653.61,4114.65 3652.87,4113.21 3652.52,4111.65 3643.14,4121.03 3644.7,4121.38 3646.14,4122.12 3647.47,4123.12
  region net $1N3469: 3787.64,3992.09 3787.64,4002.09 3789.3,4002.14 3790.94,4002.37 3792.49,4002.86 3793.84,4003.72 3793.84,3990.45 3792.49,3991.31 3790.94,3991.81 3789.3,3992.03
  region net $1N1242: 3758.3,4287.15 3748.3,4287.15 3748.25,4288.81 3748.02,4290.45 3747.53,4292 3746.66,4293.35 3759.94,4293.35 3759.08,4292 3758.58,4290.45 3758.36,4288.81
  region net $1N1242: 3526.84,3704.36 3536.84,3704.14 3536.89,3702.49 3537.11,3700.84 3537.59,3699.3 3538.43,3697.94 3525.15,3698.17 3526.04,3699.5 3526.55,3701.05 3526.78,3702.7
  region net $1N5453: 3748.3,3185.25 3758.3,3185.25 3758.36,3183.59 3758.58,3181.95 3759.08,3180.4 3759.94,3179.05 3746.66,3179.05 3747.53,3180.4 3748.02,3181.95 3748.25,3183.59
  region net $1N5453: 4009.28,3770.15 3999.28,3770.15 3999.23,3771.81 3999,3773.45 3998.51,3775 3997.65,3776.35 4010.92,3776.35 4010.06,3775 4009.56,3773.45 4009.34,3771.81
  region net $1N5453: 3794.64,4076.74 3794.64,4086.74 3796.3,4086.79 3797.94,4087.02 3799.49,4087.51 3800.84,4088.37 3800.84,4075.1 3799.49,4075.96 3797.94,4076.46 3796.3,4076.68
  region net $1N1242: 3783.69,3521.74 3773.69,3521.74 3773.64,3523.4 3773.41,3525.04 3772.92,3526.59 3772.05,3527.94 3785.33,3527.94 3784.47,3526.59 3783.97,3525.04 3783.75,3523.4
  region net $1N3469: 3797.51,3146.25 3807.51,3146.25 3807.57,3144.59 3807.79,3142.95 3808.29,3141.4 3809.15,3140.05 3795.87,3140.05 3796.74,3141.4 3797.23,3142.95 3797.46,3144.59
  region net $1N3469: 3443.12,3709.25 3453.12,3709.25 3453.17,3707.59 3453.4,3705.95 3453.9,3704.4 3454.76,3703.05 3441.48,3703.05 3442.34,3704.4 3442.84,3705.95 3443.07,3707.59
  region net MISO: 3783.69,3584.15 3773.69,3584.15 3773.64,3585.81 3773.41,3587.45 3772.92,3589 3772.05,3590.35 3785.33,3590.35 3784.47,3589 3783.97,3587.45 3783.75,3585.81
  region net +3.3V_1: 3979.19,3714.66 ccw(c3979.19,3639.66) 3934.19,3699.66 3926.69,3722.16 3934.19,3744.66 ccw(c3979.19,3804.66) 3979.19,3729.66
  region net $1N5462: 3723.55,3606.65 cw(c3774.76,3555.43) 3774.76,3627.86 3777.69,3637.86 cw(c3777.69,3667.86) 3747.69,3667.86 3737.69,3664.93 cw(c3665.27,3664.93) 3716.48,3613.72
Inner1:
  region net +3.3V_1: 3538.09,3805.36 3548.7,3794.75 3546.97,3793.13 3545.45,3791.61 3544.83,3790.81 3544.34,3789.92 3543.99,3788.91 3543.82,3787.75 3531.09,3800.48 3532.25,3800.65 3533.26,3800.99 3534.15,3801.49 3534.96,3802.11 3536.47,3803.62
  region net +3.3V_1: 4027.44,3676.34 4016.84,3686.95 4018.57,3688.57 4020.09,3690.09 4020.7,3690.89 4021.2,3691.78 4021.54,3692.79 4021.72,3693.95 4034.44,3681.22 4033.28,3681.05 4032.27,3680.71 4031.38,3680.21 4030.58,3679.59 4029.07,3678.08
  region net +3.3V_1: 3622.52,4046.98 3611.91,4036.37 3610.29,4038.11 3608.78,4039.62 3607.97,4040.24 3607.08,4040.74 3606.07,4041.08 3604.91,4041.25 3617.64,4053.98 3617.81,4052.82 3618.16,4051.81 3618.65,4050.92 3619.27,4050.12 3620.79,4048.6
  region net +3.3V_1: 3834.87,3372.39 3845.47,3382.99 3847.1,3381.26 3848.61,3379.74 3849.41,3379.12 3850.3,3378.63 3851.31,3378.29 3852.47,3378.11 3839.75,3365.38 3839.57,3366.55 3839.23,3367.56 3838.73,3368.44 3838.12,3369.25 3836.6,3370.76
  region net $1N3469: 3631.64,4107.2 3631.64,4117.2 3633.3,4117.25 3634.94,4117.48 3636.49,4117.98 3637.84,4118.84 3637.84,4105.56 3636.49,4106.42 3634.94,4106.92 3633.3,4107.15
  region net $1N3469: 3655.75,4107.22 3648.68,4100.14 3647.47,4101.28 3646.14,4102.28 3644.7,4103.02 3643.14,4103.37 3652.52,4112.75 3652.87,4111.19 3653.61,4109.75 3654.62,4108.42
  region net $1N3469: 3787.64,3992.09 3787.64,4002.09 3789.3,4002.14 3790.94,4002.37 3792.49,4002.86 3793.84,4003.72 3793.84,3990.45 3792.49,3991.31 3790.94,3991.81 3789.3,3992.03
  region net $1N1242: 3536.69,3680.15 3526.69,3680.15 3526.64,3681.81 3526.41,3683.45 3525.92,3685 3525.05,3686.35 3538.33,3686.35 3537.47,3685 3536.97,3683.45 3536.75,3681.81
  region net $1N1242: 3766.64,3528.79 3766.64,3538.79 3768.3,3538.84 3769.94,3539.07 3771.49,3539.57 3772.84,3540.43 3772.84,3527.15 3771.49,3528.01 3769.94,3528.51 3768.3,3528.74
  region net $1N3469: 3790.46,3129.2 3790.46,3139.2 3792.12,3139.25 3793.76,3139.48 3795.31,3139.98 3796.66,3140.84 3796.66,3127.56 3795.31,3128.42 3793.76,3128.92 3792.12,3129.15
  region net $1N3469: 3460.17,3702.2 3460.17,3692.2 3458.51,3692.15 3456.87,3691.92 3455.32,3691.42 3453.97,3690.56 3453.97,3703.84 3455.32,3702.98 3456.87,3702.48 3458.51,3702.25
  region net MISO: 3766.64,3591.2 3766.64,3601.2 3768.3,3601.25 3769.94,3601.48 3771.49,3601.98 3772.84,3602.84 3772.84,3589.56 3771.49,3590.42 3769.94,3590.92 3768.3,3591.15
  region net MISO: 3574.75,3775.81 3567.68,3768.73 3566.47,3769.87 3565.14,3770.87 3563.7,3771.61 3562.14,3771.96 3571.52,3781.34 3571.87,3779.78 3572.61,3778.34 3573.62,3777.01
  region net +3.3V_1: 3820.19,3576.7 ccw(c3745.19,3576.7) 3805.19,3621.7 3827.69,3629.2 3850.19,3621.7 ccw(c3910.19,3576.7) 3835.19,3576.7
  region net $1N3469: 3448.12,3692.2 cw(c3440.72,3618.88) 3492.83,3670.99 3499.91,3678.06 cw(c3551.12,3729.27) 3478.69,3729.27 3468.69,3732.2 cw(c3436.53,3732.2) 3448.12,3702.2
  region net +3.3V_1: 3591.88,3856.03 ccw(c3591.88,3920.77) 3633.31,3871.03 3640.81,3848.53 3633.31,3826.03 ccw(c3591.88,3776.3) 3591.88,3841.03
Inner2:
  region net $1N1242: 3758.3,4287.15 3748.3,4287.15 3748.25,4288.81 3748.02,4290.45 3747.53,4292 3746.66,4293.35 3759.94,4293.35 3759.08,4292 3758.58,4290.45 3758.36,4288.81
  region net $1N1242: 3526.69,3704.25 3536.69,3704.25 3536.75,3702.59 3536.97,3700.95 3537.47,3699.4 3538.33,3698.05 3525.05,3698.05 3525.92,3699.4 3526.41,3700.95 3526.64,3702.59
  region net $1N5453: 3748.3,3185.25 3758.3,3185.25 3758.36,3183.59 3758.58,3181.95 3759.08,3180.4 3759.94,3179.05 3746.66,3179.05 3747.53,3180.4 3748.02,3181.95 3748.25,3183.59
  region net $1N5453: 3992.23,3777.2 3992.23,3787.2 3993.89,3787.25 3995.53,3787.48 3997.08,3787.98 3998.43,3788.84 3998.43,3775.56 3997.08,3776.42 3995.53,3776.92 3993.89,3777.15
  region net $1N5453: 3818.75,4076.75 3811.68,4069.68 3810.47,4070.81 3809.14,4071.82 3807.7,4072.56 3806.14,4072.9 3815.52,4082.29 3815.87,4080.73 3816.61,4079.28 3817.62,4077.96
  region net $1N5453: 3978.76,3787.2 cw(c3978.76,3859.63) 3927.55,3808.41 3918.41,3803.41 cw(c3897.19,3782.2) 3918.41,3760.99 3927.55,3755.99 cw(c3978.76,3704.77) 3978.76,3777.2
Bottom Layer:
  region net U: 4224.69,3874.2 4224.69,3904.2 4227.67,3904.33 4230.42,3904.69 4232.96,3905.28 4235.32,3906.08 4237.52,3907.08 4239.6,3908.24 4241.57,3909.57 4243.47,3911.05 4247.15,3914.36 4250.85,3918.06 4254.77,3922.02 4259.14,3926.11 4259.14,3852.29 4254.77,3856.38 4250.85,3860.34 4247.15,3864.04 4243.47,3867.35 4241.57,3868.83 4239.6,3870.16 4237.52,3871.32 4235.32,3872.32 4232.96,3873.12 4230.42,3873.71 4227.67,3874.07
  region net V: 4224.69,3724.2 4224.69,3754.2 4227.67,3754.33 4230.42,3754.69 4232.96,3755.28 4235.32,3756.08 4237.52,3757.08 4239.6,3758.24 4241.57,3759.57 4243.47,3761.05 4247.15,3764.36 4250.85,3768.06 4254.77,3772.02 4259.14,3776.11 4259.14,3702.29 4254.77,3706.38 4250.85,3710.34 4247.15,3714.04 4243.47,3717.35 4241.57,3718.83 4239.6,3720.16 4237.52,3721.32 4235.32,3722.32 4232.96,3723.12 4230.42,3723.71 4227.67,3724.07
  region net W: 4224.69,3574.2 4224.69,3604.2 4227.67,3604.33 4230.42,3604.69 4232.96,3605.28 4235.32,3606.08 4237.52,3607.08 4239.6,3608.24 4241.57,3609.57 4243.47,3611.05 4247.15,3614.36 4250.85,3618.06 4254.77,3622.02 4259.14,3626.11 4259.14,3552.29 4254.77,3556.38 4250.85,3560.34 4247.15,3564.04 4243.47,3567.35 4241.57,3568.83 4239.6,3570.16 4237.52,3571.32 4235.32,3572.32 4232.96,3573.12 4230.42,3573.71 4227.67,3574.07
  region net W: 3232.69,3604.2 3232.69,3574.2 3229.71,3574.07 3226.97,3573.71 3224.43,3573.12 3222.07,3572.32 3219.87,3571.32 3217.79,3570.16 3215.81,3568.83 3213.91,3567.35 3210.23,3564.04 3206.54,3560.34 3202.61,3556.38 3198.24,3552.29 3198.24,3626.11 3202.61,3622.02 3206.54,3618.06 3210.23,3614.36 3213.91,3611.05 3215.81,3609.57 3217.79,3608.24 3219.87,3607.08 3222.07,3606.08 3224.43,3605.28 3226.97,3604.69 3229.71,3604.33
  region net V: 3232.69,3754.2 3232.69,3724.2 3229.71,3724.07 3226.97,3723.71 3224.43,3723.12 3222.07,3722.32 3219.87,3721.32 3217.79,3720.16 3215.81,3718.83 3213.91,3717.35 3210.23,3714.04 3206.54,3710.34 3202.61,3706.38 3198.24,3702.29 3198.24,3776.11 3202.61,3772.02 3206.54,3768.06 3210.23,3764.36 3213.91,3761.05 3215.81,3759.57 3217.79,3758.24 3219.87,3757.08 3222.07,3756.08 3224.43,3755.28 3226.97,3754.69 3229.71,3754.33
  region net U: 3232.69,3904.2 3232.69,3874.2 3229.71,3874.07 3226.97,3873.71 3224.43,3873.12 3222.07,3872.32 3219.87,3871.32 3217.79,3870.16 3215.81,3868.83 3213.91,3867.35 3210.23,3864.04 3206.54,3860.34 3202.61,3856.38 3198.24,3852.29 3198.24,3926.11 3202.61,3922.02 3206.54,3918.06 3210.23,3914.36 3213.91,3911.05 3215.81,3909.57 3217.79,3908.24 3219.87,3907.08 3222.07,3906.08 3224.43,3905.28 3226.97,3904.69 3229.71,3904.33
  region net W: 3664.48,3332.32 3694.48,3332.32 ccw(c5048.46,3332.32) 3695.23,3287.32 3663.73,3287.32 ccw(c2310.5,3332.32)
  region net U: 3762.9,3332.32 3792.9,3332.32 ccw(c5146.88,3332.32) 3793.65,3287.32 3762.15,3287.32 ccw(c2408.92,3332.32)
  region net W: 3792.9,4146.08 3762.9,4146.08 ccw(c2408.92,4146.08) 3762.15,4191.08 3793.65,4191.08 ccw(c5146.88,4146.08)
  region net V: 3743.69,4146.08 3713.69,4146.08 ccw(c2359.71,4146.08) 3712.94,4191.08 3744.44,4191.08 ccw(c5097.67,4146.08)
  region net U: 3694.48,4146.08 3664.48,4146.08 ccw(c2310.5,4146.08) 3663.73,4191.08 3695.23,4191.08 ccw(c5048.46,4146.08)
  region net W: 3762.9,3690.79 cw(c3732.9,3698.58) 3732.9,3667.59 3777.9,3652.59 3822.9,3667.59 cw(c3822.9,3698.58) 3792.9,3690.79
  region net V: 3713.7,3772.9 cw(c3683.7,3787.62) 3683.7,3754.2 3728.7,3739.2 3773.7,3754.2 cw(c3773.7,3787.62) 3743.7,3772.9
  region net U: 3694.65,3912.16 ccw(c3794.5,3912.16) 3724.65,3840.81 3679.65,3825.81 3634.65,3840.81 ccw(c3564.81,3912.16) 3664.65,3912.16

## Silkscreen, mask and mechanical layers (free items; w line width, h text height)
Top Silkscreen Layer:
  circle w8: c3289.69,3129.1 r15
  circle w8: c3289.69,3129.1 r8
  circle w8: c4167.71,4349.3 r8
  circle w8: c4167.71,4349.3 r15
  lines w10: 3289.69,3129.1 3317.97,3100.82 3499.6,3100.82 ; 3957.8,4377.58 4139.43,4377.58 4167.71,4349.3
  lines w30: 3117.86,3479.55 3165.69,3431.72 3213.53,3479.55 ; 3117.86,3998.85 3165.69,4046.68 3213.53,3998.85 ; 4243.86,3479.55 4291.69,3431.72 4339.53,3479.55 ; 4243.86,3998.85 4291.69,4046.68 4339.53,3998.85
  text "M3x4" at 4123,4372.6 h60 r180
  text "CS" at 3686.17,4161.55 h40 r135
  text "3.3" at 3641.08,4157.23 h40 r135
  text "SCK" at 3744.76,4152.36 h40 r135
  text "GND" at 3892.96,4152.36 h40 r135
  text "MISO" at 3799.22,4147.3 h40 r135
  text "MOSI" at 3848.62,4147.3 h40 r135
  text "MOSI" at 3607.77,3330.1 h40 r315
  text "MISO" at 3657.17,3330.1 h40 r315
  text "GND" at 3563.42,3325.04 h40 r315
  text "SCK" at 3711.62,3325.04 h40 r315
  text "3.3" at 3815.3,3320.17 h40 r315
  text "CS" at 3770.21,3315.85 h40 r315
  text "M3x4" at 3334.4,3105.8 h60
Bottom Silkscreen Layer:
  lines w10: 3702.22,3424.2 3728.2,3409.2 ; 3703.2,4054.2 3729.18,4069.2 ; 3728.2,3379.2 3728.2,3409.2 ; 3729.18,4099.2 3729.18,4069.2 ; 3754.18,3424.2 3728.2,3409.2 ; 3755.16,4054.2 3729.18,4069.2
  lines w30: 3117.87,3433.71 3165.7,3385.88 3213.54,3433.71 ; 3117.87,4043.01 3165.7,4090.84 3213.54,4043.01 ; 3473.16,4301.75 3425.33,4349.58 3473.16,4397.42 ; 3473.26,3085.97 3425.43,3133.8 3473.26,3181.64 ; 3623.3,3350.22 3701.24,3395.22 ; 3625.28,4128.18 3703.22,4083.18 ; 3728.7,3439.22 3728.7,3529.22 ; 3728.68,3949.18 3728.68,4039.18 ; 3754.17,3395.22 3832.11,3350.22 ; 3756.15,4083.18 3834.09,4128.18 ; 3992.46,4301.75 4040.29,4349.58 3992.46,4397.42 ; 3992.56,3085.97 4040.39,3133.8 3992.56,3181.64 ; 4243.87,3433.71 4291.7,3385.88 4339.54,3433.71 ; 4243.87,4043.01 4291.7,4090.84 4339.54,4043.01
  text "JLCJLCJLCJLC" at 3088.68,3889.2 h39.37 r90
